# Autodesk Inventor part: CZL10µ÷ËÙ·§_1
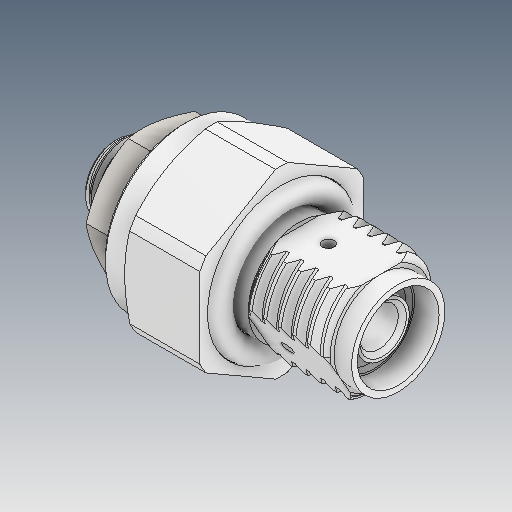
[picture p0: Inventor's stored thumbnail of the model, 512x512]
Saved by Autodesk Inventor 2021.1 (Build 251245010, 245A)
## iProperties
Created: 2021-05
Part Number: CZL10µ÷ËÙ·§_1
Material: Ogólny
Document SubType Name: Modeling
Designer: user
Density: 1 g/cm^3
Appearance: Domyślna
Author: user
Revision Number: ÈÎºÎ
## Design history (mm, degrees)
feature "ÊäÈë1"
feature "ÊäÈë4"
feature "ÊäÈë5"
node "Bryła1"
node "Bryła2"
node "Bryła3"
